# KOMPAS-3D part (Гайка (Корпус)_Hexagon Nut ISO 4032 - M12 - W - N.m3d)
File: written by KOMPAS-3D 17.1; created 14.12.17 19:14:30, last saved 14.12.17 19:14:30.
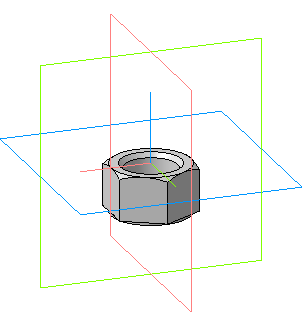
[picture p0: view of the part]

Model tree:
1. Операция без истории:1  (labels: Гайка (Корпус)_Hexagon Nut ISO 4032 - M12 - W - N)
